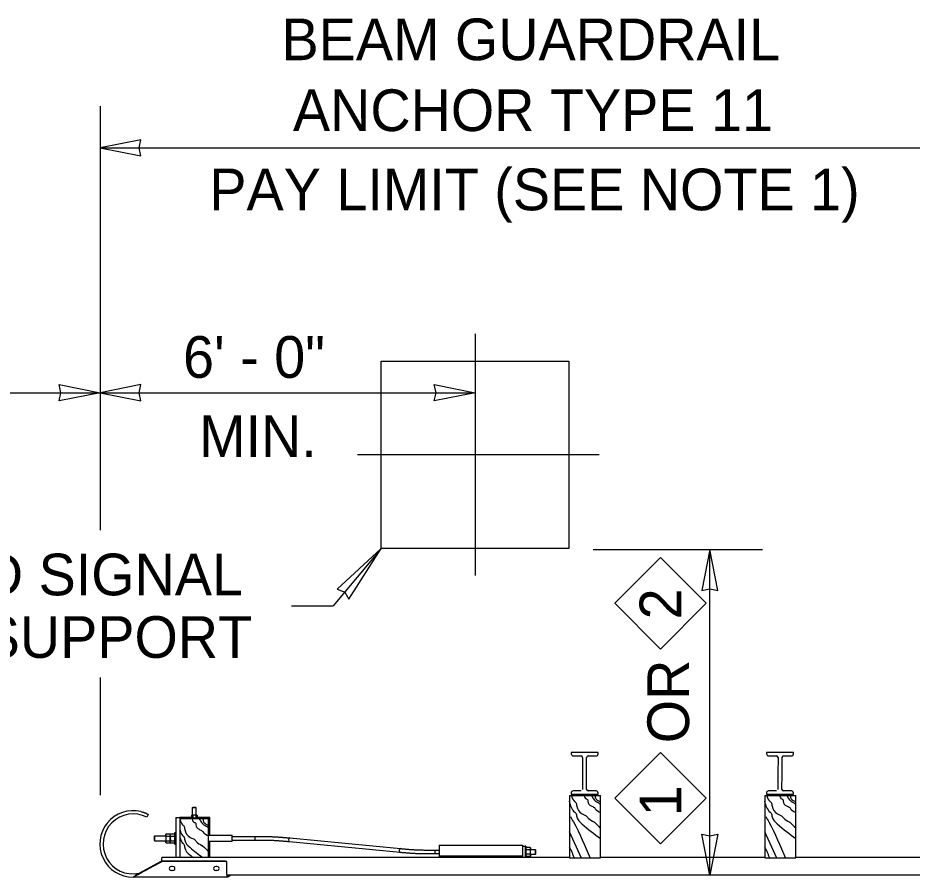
# Model space of a CAD drawing. Extents: x 99862 to 103680, y 99470 to 102076.
# Drawn here: x 100300.8 to 100644.1, y 100460.7 to 100790.5 of the extents above; entities that cross this region are included whole.
import ezdxf

# ---------------------------------------------------------------- set-up
doc = ezdxf.new("R2010")
doc.units = 0
for name, color, linetype in [('Level 10', 7, 'Continuous'), ('Level 13', 7, 'Continuous'), ('Level 15', 7, 'Continuous'), ('Level 2', 7, 'Continuous'), ('Level 20', 7, 'Continuous'), ('Level 3', 7, 'Continuous'), ('Level 4', 7, 'Continuous'), ('Level 5', 7, 'Continuous'), ('Level 6', 7, 'Continuous'), ('Level 7', 7, 'Continuous'), ('Level 9', 7, 'Continuous')]:
    doc.layers.add(name, color=color, linetype=linetype)

msp = doc.modelspace()

# ---------------------------------------------------------------- linework, layer by layer
at = {"layer": 'Level 10'}
for p, q in [((100512.55, 100492.08), (100512.55, 100468.08)), ((100512.55, 100492.08), (100524.55, 100492.08)), ((100524.55, 100468.08), (100524.55, 100492.08)), ((100587.55, 100492.08), (100587.55, 100468.08)), ((100587.55, 100492.08), (100599.55, 100492.08)), ((100599.55, 100468.08), (100599.55, 100492.08)), ((100512.55, 100468.08), (100524.55, 100468.08)), ((100517.61, 100468), (100517.61, 100468.08)), ((100517.61, 100468), (100517.61, 100468.08)), ((100519.49, 100468.08), (100519.49, 100468)), ((100519.49, 100468.08), (100519.49, 100468)), ((100587.55, 100468.08), (100599.55, 100468.08)), ((100592.61, 100468), (100592.61, 100468.08)), ((100592.61, 100468), (100592.61, 100468.08)), ((100594.49, 100468.08), (100594.49, 100468)), ((100594.49, 100468.08), (100594.49, 100468))]:
    msp.add_line(p, q, dxfattribs=at)
at = {"layer": 'Level 13'}
for p, q in [((100440.36, 100586.8), (100440.36, 100658.8)), ((100440.36, 100658.8), (100512.36, 100658.8)), ((100512.36, 100658.8), (100512.36, 100586.8)), ((100512.36, 100586.8), (100440.36, 100586.8)), ((100512.42, 100478.17), (100517.02, 100468.16)), ((100587.42, 100478.17), (100592.02, 100468.16))]:
    msp.add_line(p, q, dxfattribs=at)
for points in [[(100512.49, 100489.81), (100514.59, 100485.67), (100515.04, 100485.26), (100515.4, 100483.87), (100517.34, 100481.16), (100524.55, 100475.57)], [(100513.31, 100492.07), (100514.58, 100489.79), (100515.03, 100489.39), (100515.39, 100488), (100517.51, 100484.97), (100519.42, 100483.88), (100519.83, 100483.34), (100521.96, 100481.89), (100522.15, 100481.75), (100524.57, 100479.47)], [(100518.28, 100492.07), (100519.09, 100490.71), (100519.49, 100490.55), (100519.66, 100489.83), (100520.9, 100488.07), (100522.14, 100487.41), (100522.47, 100486.97), (100524.53, 100485.56)], [(100520.97, 100492.09), (100521.39, 100491.4), (100522.29, 100490.11), (100523.28, 100489.51), (100524.45, 100488.78)], [(100522.39, 100492.05), (100522.74, 100490.73), (100524.45, 100489.61)], [(100587.49, 100489.81), (100589.59, 100485.67), (100590.04, 100485.26), (100590.4, 100483.87), (100592.34, 100481.16), (100599.55, 100475.57)], [(100588.31, 100492.07), (100589.58, 100489.79), (100590.03, 100489.39), (100590.39, 100488), (100592.51, 100484.97), (100594.42, 100483.88), (100594.83, 100483.34), (100596.96, 100481.89), (100597.15, 100481.75), (100599.57, 100479.47)], [(100593.28, 100492.07), (100594.09, 100490.71), (100594.49, 100490.55), (100594.66, 100489.83), (100595.9, 100488.07), (100597.14, 100487.41), (100597.47, 100486.97), (100599.53, 100485.56)], [(100595.97, 100492.09), (100596.39, 100491.4), (100597.29, 100490.11), (100598.28, 100489.51), (100599.45, 100488.78)], [(100597.39, 100492.05), (100597.74, 100490.73), (100599.45, 100489.61)], [(100363.12, 100482.67), (100364.08, 100480.79), (100364.53, 100480.39), (100364.89, 100479), (100367.01, 100475.97), (100368.92, 100474.88), (100369.33, 100474.34), (100371.46, 100472.89), (100371.65, 100472.75), (100374.07, 100470.47)], [(100367.78, 100483.07), (100368.59, 100481.71), (100368.99, 100481.55), (100369.16, 100480.83), (100370.4, 100479.07), (100371.64, 100478.41), (100371.97, 100477.97), (100374.03, 100476.56)], [(100370.47, 100483.09), (100370.89, 100482.4), (100371.79, 100481.11), (100372.78, 100480.51), (100373.95, 100479.78)], [(100371.89, 100483.05), (100372.24, 100481.73), (100373.95, 100480.61)], [(100512.95, 100483.95), (100514.1, 100481.94), (100520.51, 100468.02)], [(100587.95, 100483.95), (100589.1, 100481.94), (100595.51, 100468.02)], [(100363.1, 100478.7), (100364.09, 100476.67), (100364.54, 100476.26), (100364.9, 100474.87), (100366.84, 100472.16), (100371.84, 100468.25)], [(100363.1, 100475.8), (100364.09, 100473.77), (100364.54, 100473.36), (100364.9, 100471.98), (100366.84, 100469.26), (100368.21, 100468.19)], [(100512.53, 100472.24), (100512.68, 100471.98), (100512.83, 100471.72), (100513.1, 100471.18), (100513.59, 100470.07), (100514.04, 100468.94), (100514.28, 100468.37), (100514.52, 100467.82)], [(100587.53, 100472.24), (100587.68, 100471.98), (100587.83, 100471.72), (100588.1, 100471.18), (100588.59, 100470.07), (100589.04, 100468.94), (100589.28, 100468.37), (100589.52, 100467.82)]]:
    msp.add_spline(points, degree=3, dxfattribs=at)
at = {"layer": 'Level 15'}
for p, q in [((100332.36, 100756.65), (100332.36, 100593.87)), ((100332.36, 100740.65), (100668.55, 100740.65)), ((100476.36, 100669.22), (100476.36, 100576.45)), ((100044.36, 100646.65), (100332.36, 100646.65)), ((100332.36, 100646.65), (100476.36, 100646.65)), ((100523.99, 100622.8), (100431.23, 100622.8)), ((100440.36, 100586.8), (100421.9, 100564.87)), ((100521.66, 100586.42), (100586.69, 100586.42)), ((100566.51, 100461.45), (100566.51, 100586.42)), ((100405.9, 100564.87), (100421.9, 100564.87)), ((100332.36, 100537.3), (100332.36, 100492.17))]:
    msp.add_line(p, q, dxfattribs=at)
for points in [[(100332.36, 100740.65), (100348.09, 100737.57), (100347.36, 100740.65), (100348.09, 100743.74)], [(100332.36, 100646.65), (100316.64, 100643.57), (100317.36, 100646.65), (100316.64, 100649.74)], [(100332.36, 100646.65), (100348.09, 100643.57), (100347.36, 100646.65), (100348.09, 100649.74)], [(100476.36, 100646.65), (100460.64, 100643.57), (100461.36, 100646.65), (100460.64, 100649.74)], [(100440.36, 100586.8), (100423.38, 100571.26), (100426.34, 100570.14), (100427.94, 100567.41)], [(100566.51, 100586.42), (100563.43, 100570.69), (100566.51, 100571.42), (100569.6, 100570.69)], [(100566.51, 100461.53), (100563.43, 100477.26), (100566.51, 100476.53), (100569.6, 100477.26)]]:
    msp.add_lwpolyline(points, close=True, dxfattribs=at)
at = {"layer": 'Level 2'}
for p, q in [((100356.05, 100468.2), (100356.05, 100468.25)), ((100512.55, 100468.25), (100356.05, 100468.25)), ((100356.05, 100466.81), (100356.05, 100468.2)), ((100512.55, 100468.2), (100356.05, 100468.2)), ((100587.55, 100468.25), (100524.55, 100468.25)), ((100681.05, 100468.25), (100599.55, 100468.25)), ((100656.05, 100461.45), (100381.03, 100461.45))]:
    msp.add_line(p, q, dxfattribs=at)
at = {"layer": 'Level 20'}
for points in [[(100529.97, 100565.82), (100547.52, 100583.38), (100565.07, 100565.82), (100547.52, 100548.27)], [(100529.97, 100491.01), (100547.52, 100508.56), (100565.07, 100491.01), (100547.52, 100473.45)]]:
    msp.add_lwpolyline(points, close=True, dxfattribs=at)
at = {"layer": 'Level 3'}
for p, q in [((100367.93, 100487.4), (100368.1, 100487.58)), ((100367.93, 100487.4), (100369.18, 100487.4)), ((100367.93, 100484.5), (100367.93, 100487.4)), ((100368.1, 100487.58), (100369, 100487.58)), ((100369, 100487.58), (100369.18, 100487.4)), ((100369.18, 100487.4), (100369.18, 100484.5)), ((100350.91, 100484.78), (100350.34, 100483.68)), ((100356.03, 100466.81), (100345.8, 100461.38)), ((100380.53, 100466.81), (100356.03, 100466.81)), ((100380.53, 100466.66), (100356.09, 100466.65)), ((100381.03, 100466.26), (100381.03, 100466.4)), ((100381.03, 100461.69), (100381.03, 100466.26)), ((100360.24, 100464.78), (100359.81, 100464.78)), ((100360.24, 100463.31), (100359.81, 100463.31)), ((100377.24, 100464.78), (100376.81, 100464.78)), ((100377.24, 100463.31), (100376.81, 100463.31)), ((100381.03, 100461.69), (100381.03, 100460.72)), ((100381.03, 100460.72), (100356.03, 100460.72))]:
    msp.add_line(p, q, dxfattribs=at)
for radius, start, end in [(12.75, 76.3846, 270.2805), (11.5, 62.498, 281.2468)]:
    msp.add_arc((100345.03, 100473.47), radius, start, end, dxfattribs=at)
for centre, major_axis, start_param, end_param in [((100380.53, 100466.4), (-0.5, 0), 3.141593, 4.712389), ((100380.53, 100466.26), (-0.5, 0), 3.141593, 4.712389), ((100359.81, 100464.04), (0.906, 0), 1.570796, 4.712389), ((100360.24, 100464.04), (0.906, 0), 4.712389, 7.853982), ((100376.81, 100464.04), (0.906, 0), 1.570796, 4.712389), ((100377.24, 100464.04), (0.906, 0), 4.712389, 7.853982)]:
    msp.add_ellipse(centre, major_axis=major_axis, ratio=0.807578, start_param=start_param, end_param=end_param, dxfattribs=at)
for points, degree in [([(100348.03, 100485.87), (100349.66, 100485.47), (100350.91, 100484.78), (100350.91, 100484.78)], 2), ([(100356.09, 100466.65), (100352.45, 100464.67), (100348.8, 100462.7), (100345.14, 100460.75), (100345.13, 100460.74), (100345.11, 100460.74), (100345.09, 100460.73)], 3), ([(100356.03, 100460.72), (100352.36, 100460.72), (100348.69, 100460.72), (100345.03, 100460.72)], 2), ([(100345.09, 100460.72), (100345.09, 100460.72), (100345.09, 100460.72), (100345.09, 100460.72)], 2), ([(100381.53, 100461.11), (100381.49, 100461.09), (100381.41, 100461.05), (100381.29, 100461.01), (100381.16, 100460.98), (100381.08, 100460.98), (100381.03, 100460.97)], 3), ([(100381.65, 100460.89), (100381.45, 100460.78), (100381.29, 100460.72), (100381.03, 100460.72)], 2), ([(100381.03, 100460.72), (100381.03, 100460.72), (100381.03, 100460.72), (100381.03, 100460.72)], 2), ([(100382.12, 100461.45), (100381.74, 100461.23), (100381.53, 100461.11)], 2), ([(100382.62, 100461.45), (100382.42, 100461.34), (100382.25, 100461.24), (100381.86, 100461.02), (100381.65, 100460.89)], 3)]:
    msp.add_open_spline(points, degree=degree, dxfattribs=at)
at = {"layer": 'Level 4'}
for p, q in [((100367.47, 100483.58), (100363.05, 100483.58)), ((100365.55, 100483.2), (100363.05, 100483.2)), ((100374.05, 100483.08), (100363.05, 100483.08)), ((100363.05, 100483.08), (100363.05, 100468.25)), ((100374.55, 100483.58), (100369.63, 100483.58)), ((100374.18, 100483.2), (100371.55, 100483.2)), ((100374.05, 100468.25), (100374.05, 100483.08)), ((100374.18, 100476.83), (100374.18, 100483.2)), ((100374.55, 100476.83), (100374.55, 100483.58)), ((100374.18, 100468.25), (100374.18, 100474.33)), ((100374.55, 100468.25), (100374.55, 100474.33))]:
    msp.add_line(p, q, dxfattribs=at)
at = {"layer": 'Level 5'}
for p, q in [((100371.55, 100483.41), (100365.55, 100483.41)), ((100365.55, 100483.41), (100365.55, 100483.08)), ((100371.55, 100483.41), (100371.55, 100483.08))]:
    msp.add_line(p, q, dxfattribs=at)
at = {"layer": 'Level 6'}
for p, q in [((100353.22, 100476.4), (100353.39, 100476.58)), ((100353.22, 100474.75), (100353.22, 100476.4)), ((100353.22, 100476.4), (100353.22, 100476.4)), ((100353.39, 100474.58), (100353.39, 100476.58)), ((100353.39, 100476.58), (100357.59, 100476.58)), ((100374.05, 100476.83), (100383.09, 100476.83)), ((100383.09, 100474.33), (100383.09, 100476.83)), ((100383.09, 100476.83), (100383.09, 100476.83)), ((100383.09, 100476.33), (100391.83, 100476.33)), ((100391.83, 100476.33), (100391.83, 100474.83)), ((100405.21, 100475.74), (100447.7, 100471.67)), ((100353.39, 100474.58), (100353.22, 100474.75)), ((100357.59, 100474.58), (100353.39, 100474.58)), ((100383.09, 100474.33), (100374.05, 100474.33)), ((100391.83, 100474.83), (100383.09, 100474.83)), ((100447.56, 100470.18), (100405.07, 100474.25)), ((100462.55, 100473), (100494.55, 100473)), ((100462.55, 100473), (100462.55, 100468.89)), ((100494.55, 100473), (100494.55, 100468.25)), ((100494.55, 100472.6), (100495.55, 100472.6)), ((100495.55, 100472.6), (100495.55, 100468.25)), ((100460.94, 100471.1), (100460.94, 100469.6)), ((100460.94, 100471.1), (100462.55, 100471.1)), ((100462.55, 100469.6), (100460.94, 100469.6)), ((100462.55, 100468.89), (100494.55, 100468.89)), ((100462.55, 100468.89), (100462.55, 100468.25)), ((100497.63, 100471.35), (100499.37, 100471.35)), ((100499.37, 100469.35), (100497.63, 100469.35)), ((100499.37, 100471.35), (100499.37, 100469.35)), ((100499.37, 100471.35), (100499.55, 100471.17)), ((100499.55, 100469.52), (100499.37, 100469.35)), ((100499.55, 100471.17), (100499.55, 100469.52)), ((100499.55, 100469.52), (100499.55, 100469.52))]:
    msp.add_line(p, q, dxfattribs=at)
for centre, start_param in [((100405.14, 100475), 3.141597), ((100447.63, 100470.93), 3.141588)]:
    msp.add_ellipse(centre, major_axis=(-0.072, -0.747), ratio=0.548823, start_param=start_param, end_param=6.283185, dxfattribs=at)
for points in [[(100391.83, 100476.33), (100396.55, 100476.33), (100401.27, 100476.12), (100405.21, 100475.74)], [(100405.07, 100474.25), (100401.18, 100474.62), (100396.51, 100474.83), (100391.83, 100474.83)], [(100460.94, 100469.6), (100456.21, 100469.6), (100451.5, 100469.8), (100447.56, 100470.18)], [(100447.7, 100471.67), (100451.59, 100471.3), (100456.26, 100471.1), (100460.94, 100471.1)]]:
    msp.add_open_spline(points, degree=2, dxfattribs=at)
at = {"layer": 'Level 7'}
for p, q in [((100361.43, 100483.58), (100361.43, 100468.25)), ((100361.43, 100483.58), (100363.05, 100483.58)), ((100363.05, 100483.58), (100363.05, 100483.08))]:
    msp.add_line(p, q, dxfattribs=at)
at = {"layer": 'Level 9'}
for p, q in [((100517.65, 100506.65), (100517.64, 100500.51)), ((100519.19, 100500.51), (100519.19, 100506.65)), ((100592.65, 100506.65), (100592.64, 100500.51)), ((100594.19, 100500.51), (100594.19, 100506.65)), ((100517.64, 100500.51), (100517.64, 100494.37)), ((100519.18, 100494.37), (100519.19, 100500.51)), ((100592.64, 100500.51), (100592.64, 100494.37)), ((100594.18, 100494.37), (100594.19, 100500.51)), ((100367.47, 100484.42), (100367.61, 100484.5)), ((100367.47, 100484.42), (100367.47, 100483.41)), ((100368.55, 100484.5), (100367.61, 100484.5)), ((100368.01, 100484.42), (100368.01, 100483.41)), ((100369.35, 100484.5), (100368.55, 100484.5)), ((100369.09, 100484.42), (100369.09, 100483.41)), ((100369.18, 100485.19), (100369.18, 100485.19)), ((100369.18, 100485.19), (100369.18, 100485.19)), ((100369.35, 100484.5), (100369.37, 100484.5)), ((100369.49, 100484.5), (100369.37, 100484.5)), ((100369.49, 100484.5), (100369.63, 100484.42)), ((100369.63, 100484.42), (100369.63, 100483.41)), ((100374.05, 100482.2), (100374.18, 100482.2)), ((100374.18, 100480.95), (100374.05, 100480.95)), ((100357.59, 100477.08), (100357.73, 100477.31)), ((100357.59, 100477.08), (100357.59, 100476.89)), ((100357.59, 100476.86), (100357.59, 100476.89)), ((100357.59, 100476.86), (100357.59, 100475.58)), ((100357.59, 100475.58), (100357.59, 100474.08)), ((100357.73, 100477.31), (100359.34, 100477.31)), ((100357.73, 100476.44), (100359.34, 100476.44)), ((100359.34, 100477.08), (100359.48, 100477.31)), ((100359.34, 100476.44), (100359.34, 100477.31)), ((100359.34, 100476.86), (100359.34, 100476.89)), ((100359.34, 100474.71), (100359.34, 100476.44)), ((100359.34, 100475.58), (100359.34, 100475.57)), ((100359.34, 100475.58), (100359.34, 100475.58)), ((100359.48, 100477.31), (100361.09, 100477.31)), ((100359.48, 100476.44), (100361.09, 100476.44)), ((100361.09, 100477.8), (100361.43, 100477.8)), ((100361.09, 100473.36), (100361.09, 100477.8)), ((100361.09, 100477.31), (100361.09, 100477.8)), ((100361.09, 100476.44), (100361.09, 100477.31)), ((100361.09, 100474.71), (100361.09, 100476.44)), ((100357.73, 100473.85), (100357.59, 100474.08)), ((100357.73, 100474.71), (100359.34, 100474.71)), ((100357.73, 100473.85), (100359.34, 100473.85)), ((100359.34, 100473.85), (100359.34, 100474.71)), ((100359.48, 100473.85), (100359.34, 100474.08)), ((100359.48, 100474.71), (100361.09, 100474.71)), ((100359.48, 100473.85), (100361.09, 100473.85)), ((100361.09, 100473.85), (100361.09, 100474.71)), ((100361.09, 100473.36), (100361.43, 100473.36)), ((100495.88, 100472.57), (100495.55, 100472.57)), ((100495.88, 100472.57), (100495.88, 100468.25)), ((100497.5, 100472.08), (100495.88, 100472.08)), ((100495.88, 100472.08), (100495.88, 100471.21)), ((100497.5, 100472.08), (100497.63, 100471.85)), ((100497.63, 100470.35), (100497.63, 100471.85)), ((100497.5, 100471.21), (100495.88, 100471.21)), ((100495.88, 100471.21), (100495.88, 100469.48)), ((100495.88, 100469.48), (100495.88, 100468.62)), ((100497.5, 100469.48), (100495.88, 100469.48)), ((100495.88, 100468.62), (100495.88, 100468.25)), ((100497.5, 100468.62), (100495.88, 100468.62)), ((100497.63, 100468.85), (100497.5, 100468.62)), ((100497.63, 100469.06), (100497.63, 100470.35)), ((100497.63, 100469.06), (100497.63, 100469.03)), ((100497.63, 100468.85), (100497.63, 100469.03))]:
    msp.add_line(p, q, dxfattribs=at)
for points in [[(100518.43, 100508.51), (100513.26, 100508.52), (100513.26, 100508.03)], [(100514.04, 100507.24), (100517.06, 100507.24)], [(100523.59, 100508.02), (100523.6, 100508.5), (100518.43, 100508.51)], [(100519.79, 100507.24), (100522.81, 100507.23)], [(100593.43, 100508.51), (100588.26, 100508.52), (100588.26, 100508.03)], [(100589.04, 100507.24), (100592.06, 100507.24)], [(100598.59, 100508.02), (100598.6, 100508.5), (100593.43, 100508.51)], [(100594.79, 100507.24), (100597.81, 100507.23)], [(100513.24, 100493), (100513.24, 100492.52), (100518.41, 100492.51)], [(100517.04, 100493.78), (100514.03, 100493.79)], [(100518.41, 100492.51), (100523.57, 100492.5), (100523.58, 100492.99)], [(100522.79, 100493.78), (100519.77, 100493.78)], [(100588.24, 100493), (100588.24, 100492.52), (100593.41, 100492.51)], [(100592.04, 100493.78), (100589.03, 100493.79)], [(100593.41, 100492.51), (100598.57, 100492.5), (100598.58, 100492.99)], [(100597.79, 100493.78), (100594.77, 100493.78)]]:
    msp.add_lwpolyline(points, dxfattribs=at)
for centre, radius, start, end in [((100514.04, 100508.03), 0.788, 179.9273, 269.9273), ((100517.06, 100506.65), 0.591, 359.9273, 89.9273), ((100519.79, 100506.64), 0.591, 89.9273, 179.9273), ((100522.81, 100508.02), 0.788, 269.9273, 359.9273), ((100589.04, 100508.03), 0.788, 179.9273, 269.9273), ((100592.06, 100506.65), 0.591, 359.9273, 89.9273), ((100594.79, 100506.64), 0.591, 89.9273, 179.9273), ((100597.81, 100508.02), 0.788, 269.9273, 359.9273), ((100514.02, 100493), 0.788, 89.9273, 179.9478), ((100519.77, 100494.37), 0.591, 179.9273, 269.9273), ((100522.79, 100492.99), 0.788, 359.9478, 89.9273), ((100589.02, 100493), 0.788, 89.9273, 179.9478), ((100594.77, 100494.37), 0.591, 179.9273, 269.9273), ((100597.79, 100492.99), 0.788, 359.9478, 89.9273)]:
    msp.add_arc(centre, radius, start, end, dxfattribs=at)
for points, degree in [([(100367.47, 100484.42), (100367.56, 100484.47), (100367.65, 100484.5), (100367.83, 100484.5), (100367.92, 100484.47), (100368.01, 100484.42)], 3), ([(100367.47, 100484.42), (100367.47, 100484.42), (100367.47, 100484.42), (100367.47, 100484.42)], 2), ([(100368.55, 100484.5), (100368.37, 100484.5), (100368.18, 100484.47), (100368.01, 100484.42)], 2), ([(100369.09, 100484.42), (100368.92, 100484.47), (100368.73, 100484.5), (100368.55, 100484.5)], 2), ([(100369.09, 100484.42), (100369.18, 100484.47), (100369.26, 100484.5), (100369.35, 100484.5)], 2), ([(100369.37, 100484.5), (100369.46, 100484.5), (100369.55, 100484.47), (100369.63, 100484.42)], 2), ([(100369.63, 100484.42), (100369.63, 100484.42), (100369.63, 100484.42), (100369.63, 100484.42)], 2), ([(100357.59, 100476.89), (100357.6, 100477.03), (100357.65, 100477.17), (100357.73, 100477.31)], 2), ([(100357.73, 100476.44), (100357.65, 100476.58), (100357.6, 100476.72), (100357.59, 100476.86)], 2), ([(100357.73, 100476.44), (100357.64, 100476.16), (100357.59, 100475.87), (100357.59, 100475.58)], 2), ([(100357.59, 100475.58), (100357.59, 100475.28), (100357.64, 100474.99), (100357.73, 100474.71)], 2), ([(100359.34, 100476.89), (100359.35, 100477.03), (100359.4, 100477.17), (100359.48, 100477.31)], 2), ([(100359.48, 100476.44), (100359.4, 100476.58), (100359.35, 100476.72), (100359.34, 100476.86)], 2), ([(100359.48, 100476.44), (100359.39, 100476.16), (100359.34, 100475.87), (100359.34, 100475.58)], 2), ([(100359.34, 100475.58), (100359.34, 100475.28), (100359.39, 100474.99), (100359.48, 100474.71)], 2), ([(100357.73, 100473.85), (100357.64, 100473.99), (100357.59, 100474.13), (100357.59, 100474.42), (100357.64, 100474.57), (100357.73, 100474.71)], 3), ([(100357.73, 100473.85), (100357.73, 100473.85), (100357.73, 100473.85), (100357.73, 100473.85)], 2), ([(100359.48, 100473.85), (100359.39, 100473.99), (100359.34, 100474.13), (100359.34, 100474.42), (100359.39, 100474.57), (100359.48, 100474.71)], 3), ([(100359.48, 100473.85), (100359.48, 100473.85), (100359.48, 100473.85), (100359.48, 100473.85)], 2), ([(100497.5, 100472.08), (100497.5, 100472.08), (100497.5, 100472.08), (100497.5, 100472.08)], 2), ([(100497.5, 100472.08), (100497.58, 100471.94), (100497.63, 100471.8), (100497.63, 100471.5), (100497.58, 100471.36), (100497.5, 100471.21)], 3), ([(100497.63, 100470.35), (100497.63, 100470.64), (100497.58, 100470.93), (100497.5, 100471.21)], 2), ([(100497.5, 100469.48), (100497.58, 100469.76), (100497.63, 100470.06), (100497.63, 100470.35)], 2), ([(100497.5, 100469.48), (100497.58, 100469.35), (100497.63, 100469.21), (100497.63, 100469.06)], 2), ([(100497.63, 100469.03), (100497.63, 100468.89), (100497.58, 100468.75), (100497.5, 100468.62)], 2), ([(100497.5, 100468.62), (100497.5, 100468.62), (100497.5, 100468.62), (100497.5, 100468.62)], 2)]:
    msp.add_open_spline(points, degree=degree, dxfattribs=at)

# ---------------------------------------------------------------- texts
at = {"layer": 'Level 15'}
msp.add_text('OR', height=16, rotation=90, dxfattribs=at).set_placement((100558.51, 100512.11))
at = {"layer": 'Level 20'}
for s, p in [('BEAM GUARDRAIL', (100402.05, 100774.25)), ('ANCHOR TYPE 11', (100406.43, 100747.05)), (' PAY LIMIT (SEE NOTE 1)', (100368.4, 100716.65)), ('6\' - 0" ', (100364.24, 100652.35)), ('MIN.', (100370.4, 100621.95)), ('RAILROAD SIGNAL', (100193.45, 100568.87)), ('SUPPORT', (100287.33, 100544.87))]:
    msp.add_text(s, height=16, dxfattribs=at).set_placement(p)
for s, p in [('2', (100555.52, 100559.64)), ('1', (100555.52, 100484.05))]:
    msp.add_text(s, height=16, rotation=90, dxfattribs=at).set_placement(p)

doc.saveas('drawing.dxf')
